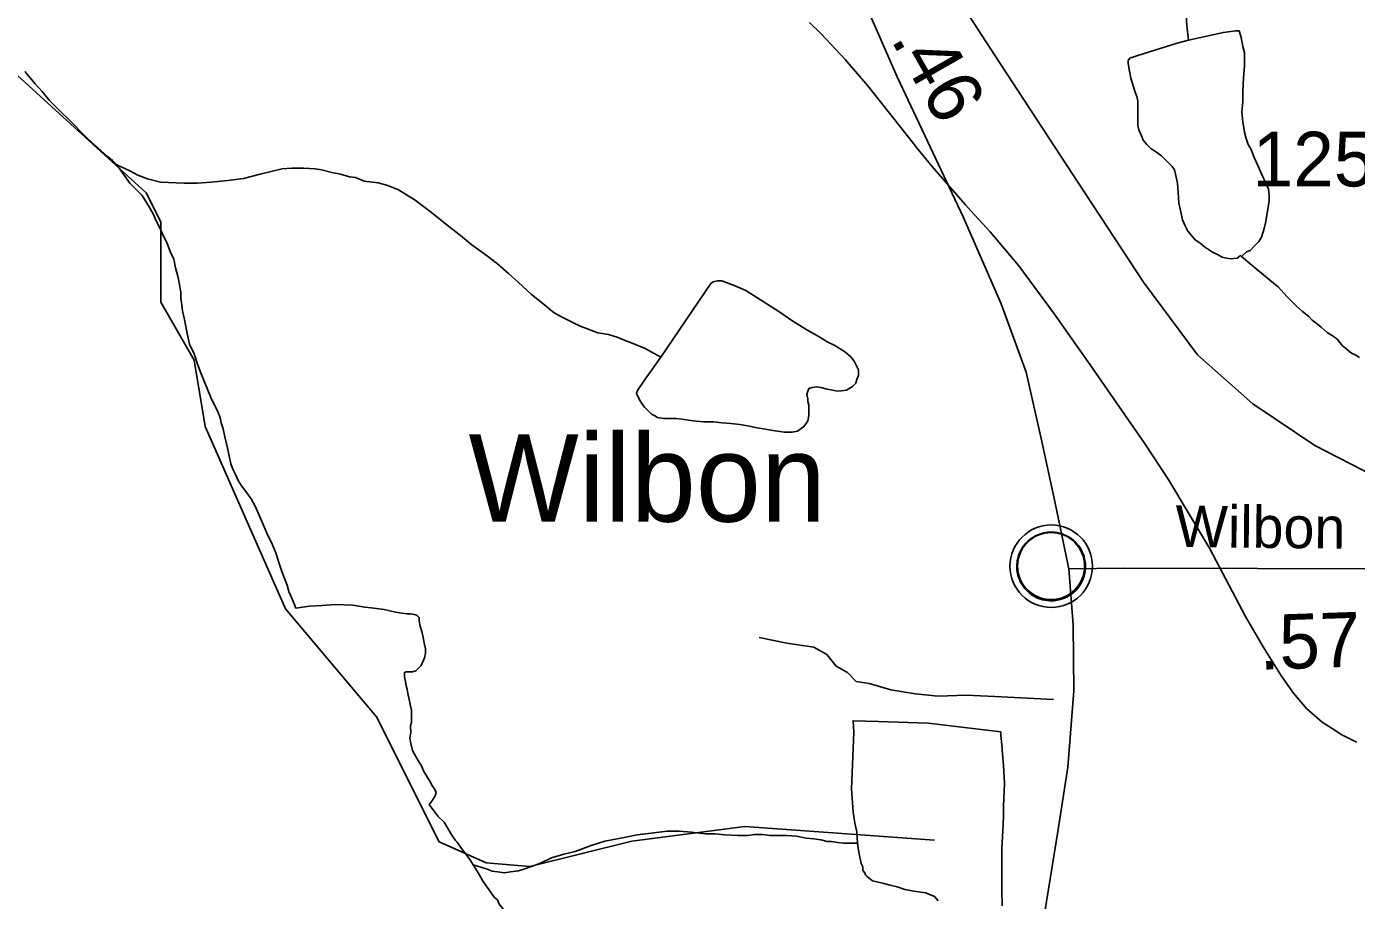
# Model space of a CAD drawing. Extents: x 2001466 to 2224147, y 644118 to 847247.
# Drawn here: x 2046028 to 2049070, y 671721 to 673718 of the extents above; entities that cross this region are included whole.
import ezdxf

# ---------------------------------------------------------------- set-up
doc = ezdxf.new("R2010")
doc.units = 0
for name, color, linetype in [('Exist Civil Demographics Community CELL', 7, 'Continuous'), ('Exist Civil Demographics Community Label', 7, 'Continuous'), ('Exist Hydrographic Creek Single Shore', 7, 'Continuous'), ('Exist Hydrographic Misc Water Feature', 7, 'Continuous'), ('Exist Railroad Mainline', 7, 'Continuous'), ('Exist Road Non-System Type 51', 7, 'Continuous'), ('Exist Road Secondary Mileage Hundredths English Label', 7, 'Continuous'), ('Exist Road Secondary Type 51 Attributed', 7, 'Continuous'), ('Exist Road Secondary Type 51 Label', 7, 'Continuous'), ('Exist Road Secondary Type 51 Number Label', 7, 'Continuous')]:
    doc.layers.add(name, color=color, linetype=linetype)

msp = doc.modelspace()

# ---------------------------------------------------------------- linework, layer by layer
at = {"layer": 'Exist Civil Demographics Community CELL'}
msp.add_lwpolyline([(2048294.1, 672497.2), (2048295.1, 672502.8), (2048296.8, 672509.4), (2048299.7, 672516.6), (2048302.7, 672522.3), (2048306, 672528.1), (2048309.8, 672533.2), (2048313.7, 672537.6), (2048318.3, 672542.2), (2048323.9, 672546.7), (2048329.3, 672550.4), (2048334.2, 672553.3), (2048339.2, 672555.7), (2048344.7, 672558), (2048350.3, 672559.8), (2048354.6, 672561), (2048359.5, 672561.7), (2048363.6, 672562.4), (2048370, 672562.7), (2048374.4, 672562.6), (2048380.1, 672562.3), (2048385, 672561.6), (2048389.9, 672560.6), (2048394.9, 672559.2), (2048400.1, 672557.3), (2048406.7, 672554.4), (2048413, 672550.9), (2048418, 672547.3), (2048423.2, 672543.3), (2048426.5, 672540.2), (2048430.6, 672535.8), (2048434.5, 672531.1), (2048437.6, 672526.5), (2048440.7, 672521.5), (2048443.2, 672516.3), (2048445.2, 672511.3), (2048446.8, 672506.3), (2048448, 672501.7), (2048449.1, 672495.7), (2048449.8, 672491), (2048450, 672485), (2048449.8, 672479.2), (2048449.3, 672473.5), (2048448.3, 672468), (2048446.7, 672461.8), (2048444.8, 672456), (2048442.5, 672450.9), (2048439.4, 672444.9), (2048436.1, 672439.6), (2048432.6, 672434.9), (2048428.4, 672430.2), (2048423.1, 672425.2), (2048418.1, 672421.1), (2048413.1, 672417.7), (2048408.8, 672415.1), (2048401.9, 672411.9), (2048394.8, 672409.2), (2048388.8, 672407.7), (2048382.2, 672406.4), (2048377.8, 672406), (2048373.3, 672405.7), (2048367.7, 672405.7), (2048363.5, 672406.1), (2048357.8, 672406.9), (2048351.9, 672408.2), (2048347.3, 672409.5), (2048342.1, 672411.3), (2048337.6, 672413.3), (2048333.6, 672415.6), (2048326.8, 672419.6), (2048321.2, 672423.9), (2048316.3, 672428.4), (2048311.9, 672433.3), (2048308.7, 672437.2), (2048305.7, 672441.4), (2048301.6, 672448.5), (2048299.9, 672452), (2048298.2, 672456.1), (2048295.6, 672464.2), (2048294.1, 672471.3), (2048293.4, 672476.5), (2048293, 672482.8), (2048293, 672487.5), (2048293.5, 672493.9)], close=True, dxfattribs=at)
for centre, radius in [((2048371.7, 672484.8), 94.3), ((2048371.4, 672485.1), 76.7)]:
    msp.add_circle(centre, radius, dxfattribs=at)
at = {"layer": 'Exist Hydrographic Creek Single Shore'}
for points in [[(2046301.5, 673338.5), (2045634.6, 673946), (2044775.7, 674383.4), (2044516.7, 674391.9), (2044450.7, 674360.5), (2044042.6, 674401.5), (2043792.7, 674367.3), (2043467.7, 674222.9), (2043350.6, 674215.5), (2042975.5, 674397), (2042625.7, 674630.5), (2042616.7, 674673.3)], [(2048104.5, 671858.3), (2047670.6, 671890.1), (2047412.4, 671856), (2047179.5, 671798.4), (2047079.4, 671807), (2046971.6, 671855.1), (2046828.5, 672140.2), (2046620.5, 672387.2), (2046436.6, 672804.3), (2046411.6, 672955.7), (2046335.5, 673088.5), (2046335.5, 673272.3), (2046301.5, 673338.5)]]:
    msp.add_lwpolyline(points, dxfattribs=at)
at = {"layer": 'Exist Hydrographic Misc Water Feature'}
msp.add_line((2049059, 672088.3), (2049070.7, 672082.3), dxfattribs=at)
for points in [[(2048685.6, 673686.9), (2048681.5, 673720.8), (2048679.5, 673754.8), (2048671.5, 673800.6), (2048657.1, 673844.6)], [(2047818.7, 673727.8), (2047844.5, 673702.5), (2047900.5, 673642.7), (2047952.6, 673582.9), (2048056.5, 673450.8), (2048063.7, 673442)], [(2047818.7, 673727.8), (2047844.5, 673702.5), (2047900.5, 673642.7), (2047952.6, 673582.9), (2048056.5, 673450.8), (2048063.7, 673442)], [(2048685.6, 673686.9), (2048765.6, 673704.8), (2048793.5, 673708.7), (2048801.5, 673708.7), (2048805.8, 673693), (2048809.7, 673673), (2048813.6, 673659), (2048813.8, 673629), (2048811.5, 673600.9), (2048809.7, 673569.1), (2048809.9, 673546.8), (2048807.8, 673522.7), (2048809.9, 673500.9), (2048813.8, 673476.8), (2048817.9, 673462.8), (2048822, 673448.8), (2048827.9, 673439), (2048836.1, 673419.1), (2048844.1, 673400.8), (2048856, 673375.1), (2048862.2, 673361.2), (2048868.3, 673346.9), (2048870.2, 673333.2), (2048870.4, 673321), (2048868.1, 673305.1), (2048866.3, 673296.9), (2048864, 673283), (2048862.4, 673273.1), (2048858.5, 673257.1), (2048856.2, 673248.9), (2048852.5, 673236.9), (2048846.2, 673226.9), (2048836.3, 673217.1), (2048826.7, 673206.8), (2048818.3, 673203.2), (2048806.8, 673193), (2048804.3, 673195.2)], [(2048804.3, 673195.2), (2048796.6, 673189.1), (2048782.6, 673187.1), (2048772.4, 673189.1), (2048762.3, 673191), (2048752.3, 673197), (2048740.6, 673202.8), (2048722.1, 673214.9), (2048712.5, 673222.9), (2048700.6, 673230.8), (2048692.6, 673240.9), (2048684.4, 673250.7), (2048678.2, 673262.9), (2048672.1, 673276.9), (2048668.4, 673294.9), (2048663.9, 673314.6), (2048662, 673338.8), (2048660.2, 673360.6), (2048656.3, 673380.7), (2048654, 673390.7), (2048648.3, 673398.5), (2048641.9, 673404.7), (2048630, 673416.7), (2048624.1, 673422.5), (2048610.2, 673432.7), (2048600.1, 673438.7), (2048590.3, 673448.7), (2048581.7, 673458.5), (2048577.8, 673468.4), (2048572, 673482.6), (2048570, 673492.3), (2048570, 673508.5), (2048570, 673520.7), (2048569.8, 673534.5), (2048570, 673548.7), (2048567.7, 673558.4), (2048563.8, 673568.3), (2048559.5, 673580.3), (2048554, 673600.6), (2048551.7, 673612.3), (2048549.7, 673620.3), (2048547.6, 673634.4), (2048547.4, 673640.5), (2048551.7, 673646.3), (2048569.8, 673652.5), (2048659.6, 673680.7), (2048685.6, 673686.9)], [(2046024.2, 673615.8), (2046048.2, 673587.8), (2046064.2, 673569.8), (2046080.2, 673549.9), (2046092.3, 673537.9), (2046108.3, 673521.9), (2046122.3, 673508), (2046138.3, 673492), (2046152.4, 673478), (2046166.3, 673464), (2046176.4, 673454.1), (2046190.5, 673442.1), (2046198.5, 673434.1), (2046212.5, 673422.2), (2046224.4, 673412.2), (2046234.6, 673402.2)], [(2048063.7, 673442), (2048098.6, 673399), (2048175.4, 673311.2), (2048188.2, 673297.2)], [(2048063.7, 673442), (2048098.6, 673399), (2048175.4, 673311.2), (2048188.2, 673297.2)], [(2046234.6, 673402.2), (2046264.6, 673388.2), (2046282.6, 673378.3), (2046304.6, 673370.3), (2046334.5, 673362.3), (2046388.6, 673360.5), (2046418.6, 673360.5), (2046450.5, 673362.6), (2046488.5, 673366.6), (2046524.6, 673370.7), (2046562.5, 673380.8), (2046612.5, 673392.9), (2046634.5, 673394.9), (2046662.4, 673395), (2046688.4, 673393), (2046702.4, 673391), (2046726.3, 673385.1), (2046746.4, 673381.1), (2046766.5, 673375.2), (2046780.5, 673373.2), (2046800.4, 673365.2), (2046832.4, 673361.3), (2046854.5, 673355.4), (2046878.5, 673345.4), (2046894.5, 673335.4), (2046916.6, 673321.5), (2046932.6, 673309.5), (2046954.6, 673293.5), (2046986.6, 673267.6), (2047016.7, 673243.7), (2047046.6, 673219.7), (2047068.8, 673203.8), (2047082.7, 673193.8), (2047104.9, 673175.8), (2047130.7, 673153.9), (2047152.9, 673133.9), (2047183, 673106), (2047204.9, 673088), (2047234.9, 673064.1), (2047252.9, 673054.1), (2047273, 673044.2), (2047292.9, 673034.3), (2047335.1, 673018.3), (2047359.1, 673014.4), (2047379, 673008.4), (2047397.1, 673000.4), (2047413.1, 672994.4), (2047443, 672982.5), (2047456.9, 672974.5), (2047479.1, 672962.5)], [(2046234.6, 673402.2), (2046264.6, 673360.2), (2046282.6, 673342.3), (2046292.7, 673332.3), (2046308.7, 673306.4), (2046318.7, 673288.4), (2046324.6, 673274.3), (2046332.8, 673258.4), (2046340.8, 673240.4), (2046348.8, 673224.4), (2046356.8, 673204.4), (2046364.8, 673186.5), (2046368.9, 673166.5), (2046374.9, 673144.5), (2046379, 673124.5), (2046381, 673110.5), (2046381, 673096.5), (2046383.1, 673082.5), (2046385.1, 673068.5), (2046389.2, 673048.6), (2046395.2, 673016.5), (2046401.1, 672992.6), (2046411.4, 672970.6), (2046419.4, 672946.6), (2046427.4, 672924.6), (2046441.5, 672890.7), (2046449.5, 672870.7), (2046457.5, 672854.7), (2046463.5, 672842.7), (2046469.6, 672828.7), (2046471.5, 672820.7), (2046473.5, 672812.7), (2046477.6, 672798.7), (2046481.5, 672780.7), (2046485.6, 672764.8), (2046487.7, 672754.8), (2046491.8, 672736.8), (2046495.7, 672718.8), (2046499.8, 672706.8), (2046505.7, 672694.8), (2046511.9, 672680.8), (2046519.9, 672668.8), (2046531.8, 672652.9), (2046541.8, 672638.9), (2046551.8, 672620.9), (2046571.9, 672575), (2046580.1, 672555), (2046588.1, 672538.9), (2046598, 672515), (2046606, 672491), (2046612.1, 672473), (2046618.1, 672457), (2046624.2, 672441.1), (2046628.1, 672427.1), (2046634.3, 672413.1), (2046640.2, 672399.1), (2046644.3, 672389.1)], [(2048188.2, 673297.2), (2048232.2, 673249), (2048297.5, 673171.6), (2048376.6, 673063.8), (2048460.5, 672944.8), (2048586.6, 672763.8)], [(2048188.2, 673297.2), (2048232.2, 673249), (2048297.5, 673171.6), (2048376.6, 673063.8), (2048460.5, 672944.8), (2048586.6, 672763.8)], [(2049076.9, 672961.6), (2049066.8, 672967.6), (2049058.6, 672971.7), (2049044.9, 672983.4), (2049036.9, 672989.5), (2049026.4, 673003.3), (2049018.6, 673009.3), (2049002.8, 673019.4), (2048988.7, 673031.3), (2048976.8, 673041.3), (2048968.4, 673047.4), (2048960.8, 673055.4), (2048946.6, 673067.3), (2048932.5, 673079.2), (2048920.4, 673091.2), (2048910.6, 673101.1), (2048890.5, 673123.3), (2048876.3, 673135.2), (2048866.7, 673143.1), (2048852.5, 673155), (2048840.4, 673164.9), (2048830.4, 673173), (2048806.8, 673193), (2048804.3, 673195.2)], [(2047479.1, 672962.5), (2047592.9, 673130.7), (2047598.8, 673134.7), (2047608.7, 673136.8), (2047618.7, 673136.8), (2047630.8, 673132.8), (2047650.7, 673124.9), (2047672.9, 673114.9), (2047748.7, 673067.1), (2047780.9, 673045.1), (2047812.9, 673025.2), (2047836.9, 673011.2), (2047860.9, 672997.2), (2047876.9, 672989.3), (2047898.8, 672975.4), (2047913, 672963.4), (2047921, 672953.4), (2047927.1, 672941.4), (2047931, 672933.4), (2047931, 672921.4), (2047927.1, 672911.4), (2047925.1, 672903.4), (2047917.1, 672895.4), (2047903.1, 672887.4), (2047891.2, 672885.4), (2047883.2, 672885.3), (2047871.2, 672887.3), (2047859.3, 672889.3), (2047845.1, 672893.2), (2047835.3, 672895.2), (2047825.2, 672893.2), (2047817.2, 672891.2), (2047815.2, 672885.2), (2047813.1, 672877.2), (2047815.2, 672867.2), (2047815.2, 672861.2), (2047817.2, 672853.2), (2047817.2, 672839.2), (2047817.2, 672829.3), (2047815.4, 672817.3), (2047811.3, 672811.3), (2047805.3, 672803.2), (2047791.4, 672793.2), (2047779.3, 672791.2), (2047761.2, 672791.1), (2047751.2, 672793.1), (2047735.2, 672795.1), (2047713.3, 672799.1), (2047699.3, 672801), (2047681.3, 672805), (2047659.3, 672809), (2047639.2, 672810.8), (2047619.3, 672812.8), (2047599.3, 672814.8), (2047577.3, 672814.8), (2047559.3, 672816.7), (2047541.2, 672818.7), (2047527.3, 672820.7), (2047513.3, 672822.7), (2047497.3, 672822.6), (2047485.2, 672822.6), (2047471.3, 672824.5), (2047465.4, 672828.5), (2047457.4, 672832.5), (2047449.4, 672840.5), (2047441.4, 672848.6), (2047435.2, 672856.5), (2047431.3, 672862.5), (2047425.4, 672874.5), (2047423.3, 672880.5), (2047425.2, 672886.5), (2047443.2, 672912.5), (2047479.1, 672962.5)], [(2048586.6, 672763.8), (2048640.5, 672681.4), (2048733.6, 672525.8), (2048816.4, 672370)], [(2048586.6, 672763.8), (2048640.5, 672681.4), (2048733.6, 672525.8), (2048816.4, 672370)], [(2046644.3, 672389.1), (2046674.3, 672393.2), (2046704.2, 672395.2), (2046734.3, 672397.3), (2046774.3, 672395.4), (2046802.2, 672391.4), (2046816.4, 672389.4), (2046846.3, 672385.5), (2046872.3, 672379.5), (2046886.3, 672377.6), (2046898.4, 672375.6), (2046906.4, 672375.6), (2046918.3, 672373.6), (2046922.4, 672371.7), (2046926.3, 672367.7), (2046926.3, 672359.7), (2046928.3, 672347.7), (2046932.2, 672335.7), (2046934.3, 672325.6), (2046938.4, 672305.7), (2046940.4, 672295.7), (2046940.4, 672285.7), (2046938.4, 672275.7), (2046936.3, 672269.7), (2046930.4, 672257.7), (2046926.5, 672253.7), (2046918.5, 672245.7), (2046910.5, 672243.7), (2046902.5, 672243.6), (2046896.5, 672243.6), (2046892.4, 672241.6), (2046892.4, 672235.6), (2046892.4, 672231.6), (2046894.5, 672221.6), (2046896.5, 672211.6), (2046898.6, 672203.6), (2046900.4, 672193.6), (2046902.7, 672183.6), (2046906.6, 672165.7), (2046908.6, 672155.7), (2046908.6, 672141.7), (2046908.6, 672127.7), (2046906.6, 672119.7), (2046906.8, 672105.7), (2046904.7, 672091.7), (2046906.8, 672079.7), (2046910.7, 672063.7), (2046918.7, 672049.6), (2046926.9, 672035.7), (2046931, 672029.8), (2046936.9, 672015.7), (2046940.8, 672009.7), (2046944.9, 672001.7), (2046950.9, 671991.8), (2046956.8, 671981.8), (2046960.9, 671975.8), (2046965, 671967.8), (2046963, 671959.8), (2046955, 671947.8), (2046949, 671939.8)], [(2048816.4, 672370), (2048856.6, 672300.2), (2048898.5, 672233.7), (2048925.7, 672194.8), (2048955.5, 672159.9), (2048991.6, 672128.4), (2049014.3, 672113.9)], [(2048816.4, 672370), (2048856.6, 672300.2), (2048898.5, 672233.7), (2048925.7, 672194.8), (2048955.5, 672159.9), (2048991.6, 672128.4), (2049014.3, 672113.9)], [(2048259.3, 671708.3), (2048259.1, 671746.3), (2048259.1, 671780.3), (2048258.9, 671812.2), (2048258.9, 671840.2), (2048261, 671880.2), (2048262.8, 671912.2), (2048262.8, 671936.2), (2048264.6, 671988.2), (2048262.6, 672030.2), (2048260.5, 672056.2), (2048258.5, 672076.2), (2048256.4, 672098.2), (2048256.4, 672106.2), (2048090.6, 672125.9), (2047976.5, 672129.6), (2047918.5, 672131.6), (2047920.6, 672105.6), (2047914.8, 671975.6), (2047916.9, 671943.6), (2047918.9, 671923.6), (2047922.8, 671897.5), (2047926.9, 671877.6), (2047929, 671851.6)], [(2049014.3, 672113.9), (2049036.5, 672099.7), (2049059, 672088.3)], [(2049014.3, 672113.9), (2049036.5, 672099.7), (2049059, 672088.3)], [(2046949, 671939.8), (2046968.9, 671913.8), (2046983.1, 671899.9), (2047001.1, 671869.9), (2047009.1, 671857.9), (2047013.2, 671853.9), (2047023.1, 671839.9), (2047033.3, 671825.9), (2047043.4, 671812), (2047049.3, 671802)], [(2047049.3, 671802), (2047069.2, 671796), (2047081.3, 671792), (2047093.2, 671788), (2047105.3, 671786.1), (2047121.3, 671784.1), (2047135.2, 671786.2), (2047153.3, 671788.1), (2047165.4, 671792.1), (2047183.2, 671798.2), (2047203.3, 671806.2), (2047229.1, 671818.3), (2047257.2, 671826.3), (2047283.1, 671832.4), (2047319.2, 671846.5), (2047351.1, 671856.5), (2047395.2, 671864.6), (2047425, 671870.7), (2047456.9, 671874.7), (2047493, 671878.8), (2047520.9, 671878.9), (2047549, 671876.9), (2047581, 671872.9), (2047602.9, 671873), (2047625.1, 671871), (2047655, 671869.1), (2047677, 671869.1), (2047693, 671871.2), (2047711, 671871.2), (2047729, 671869.2), (2047748.9, 671869.2), (2047767, 671869.3), (2047788.9, 671867.4), (2047811.1, 671863.4), (2047828.9, 671861.5), (2047845.1, 671859.5), (2047859.1, 671855.5), (2047869.1, 671855.5), (2047883, 671853.5), (2047897, 671851.6), (2047910.9, 671851.6), (2047929, 671851.6)], [(2047929, 671851.6), (2047931, 671835.6), (2047933.1, 671823.6), (2047937.2, 671805.6), (2047941.1, 671797.6), (2047941.1, 671789.6), (2047945.2, 671783.6), (2047947.2, 671779.6), (2047951.1, 671775.7), (2047955.2, 671771.7), (2047963.2, 671765.7), (2047973.1, 671763.7), (2047989.1, 671759.7), (2048003.2, 671755.8), (2048019.2, 671751.8), (2048037, 671745.8), (2048057.1, 671741.9), (2048073.1, 671739.9), (2048085.2, 671738), (2048093.2, 671734), (2048099.2, 671732), (2048105.1, 671730), (2048113.3, 671720)], [(2047049.3, 671802), (2047055.2, 671794), (2047063.2, 671780), (2047071.2, 671766.1), (2047079.4, 671754.1), (2047085.4, 671746.1), (2047089.3, 671740.1), (2047097.5, 671728.1), (2047105.5, 671722.1), (2047109.4, 671712.1), (2047117.4, 671702.1), (2047125.6, 671684.2), (2047133.6, 671668.2), (2047137.5, 671658.1), (2047143.4, 671634.2), (2047147.5, 671620.2), (2047153.7, 671596.2), (2047161.7, 671572.2), (2047165.6, 671558.2), (2047169.7, 671540.2), (2047173.8, 671520.2), (2047177.7, 671506.3)]]:
    msp.add_lwpolyline(points, dxfattribs=at)
at = {"layer": 'Exist Railroad Mainline'}
msp.add_lwpolyline([(2049760.1, 672513.6), (2049542.8, 672563.4), (2049328.5, 672623.6), (2049327.5, 672623.9), (2049110.7, 672690.4), (2048974.7, 672760.4), (2048832.7, 672856.3), (2048706.5, 672968.2), (2048582.5, 673134.4), (2048434.3, 673360.2), (2048242.3, 673654.1), (2048098.2, 673876.2), (2047956, 674070.1), (2047836, 674240.1), (2047705.8, 674398), (2047644.1, 674474.3)], dxfattribs=at)
at = {"layer": 'Exist Road Non-System Type 51'}
msp.add_lwpolyline([(2048376.7, 672180.3), (2048242.8, 672187.1), (2048176.9, 672190.4), (2048112.8, 672187.7), (2048060.9, 672192.7), (2048005.1, 672201.9), (2047955.4, 672216.9), (2047925.5, 672221.5), (2047905.9, 672241.9), (2047880.2, 672256.4), (2047858.8, 672282.9), (2047829.1, 672299.5), (2047767.3, 672308.7), (2047703.6, 672322)], dxfattribs=at)
at = {"layer": 'Exist Road Secondary Type 51 Attributed'}
for points in [[(2047662, 674855.3), (2047673.1, 674640.9), (2047684.7, 674447.6), (2047707.9, 674352.5), (2047754.9, 674212), (2047865.8, 673954.3), (2048019.3, 673603.6), (2048170.3, 673283.5), (2048256.9, 673084.9), (2048314.4, 672928.6), (2048350.3, 672770.2), (2048379.8, 672632.8), (2048412.1, 672478.6)], [(2048412.1, 672478.6), (2048539.3, 672480.7), (2048843.3, 672479.7), (2049221.7, 672478.6), (2049403.3, 672489.2), (2049721, 672510.3), (2049989.7, 672537.8), (2050182.8, 672568.4), (2050289.4, 672574.7), (2050391.8, 672564.2), (2050585.5, 672530.4), (2050759.8, 672494.2)], [(2048412.1, 672478.6), (2048421.6, 672350.8), (2048423.7, 672199.8), (2048410, 672025.5), (2048387.3, 671882.9), (2048306.6, 671384.3), (2048248, 671023), (2048189.9, 670693.5), (2048153.5, 670423), (2048109.2, 670167.4), (2048069.1, 669827.3)]]:
    msp.add_lwpolyline(points, dxfattribs=at)

# ---------------------------------------------------------------- texts
at = {"layer": 'Exist Civil Demographics Community Label'}
msp.add_text('Wilbon', height=200, dxfattribs=at).set_placement((2047038.9, 672586.6))
at = {"layer": 'Exist Road Secondary Mileage Hundredths English Label'}
for s, rotation, p in [('.46', 299.6361, (2048003.3, 673689.5)), ('.57', 1.9121, (2048848.5, 672248))]:
    msp.add_text(s, height=125, rotation=rotation, dxfattribs=at).set_placement(p)
at = {"layer": 'Exist Road Secondary Type 51 Label'}
msp.add_text('Wilbon', height=95, rotation=359.4227, dxfattribs=at).set_placement((2048655.5, 672528.8))
at = {"layer": 'Exist Road Secondary Type 51 Number Label'}
msp.add_text('1253', height=125, dxfattribs=at).set_placement((2048832.1, 673352.9))

doc.saveas('drawing.dxf')
